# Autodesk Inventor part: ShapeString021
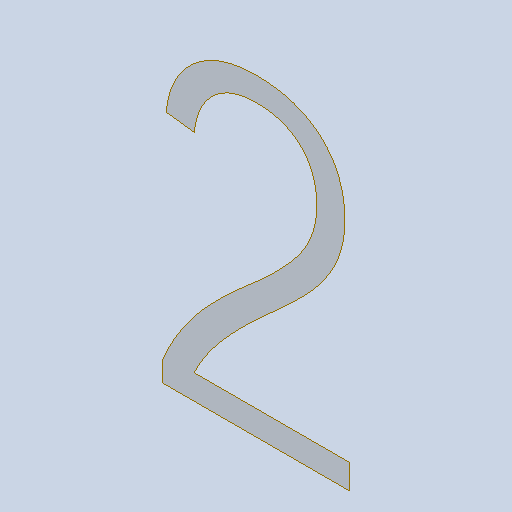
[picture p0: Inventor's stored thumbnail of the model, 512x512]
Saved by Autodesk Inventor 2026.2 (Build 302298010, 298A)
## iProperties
Created: 2026-10
Part Number: ShapeString021
Material: Générique
Document SubType Name: Modeling
Designer: mel
Density: 1 g/cm^3
Appearance: Par défaut
Author: mel
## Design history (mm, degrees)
feature "Composite1"
body "Srf1"
